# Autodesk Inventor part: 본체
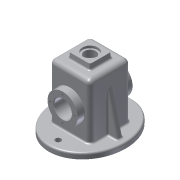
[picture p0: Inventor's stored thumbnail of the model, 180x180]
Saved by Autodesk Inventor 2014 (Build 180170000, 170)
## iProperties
Created: 2017-07
Part Number: 본체
Material: 알루미늄 6061
Document SubType Name: Modeling
Designer: user
Density: 2.71 g/cm^3
Appearance: 알루미늄 - 평지
Mass: 880.579 g
Surface Area: 992.163 cm^2
Volume: 324.937 cm^3
Author: user
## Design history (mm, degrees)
sketch "스케치1" dims "d0" = 75, "d1" = 65
  geometry: L1 (-99.161, 0)-(101.548, 0); C1 r 5 at (-58, 0); C2 r 5 at (58, 0); 2 further points; 1 other entity
  constraints: 3 point on line, 2 centre point, 2 end point, 1 coincident, 1 horizontal, 2 other
  dimensions: "d2" = 10 diameter of C1; "d3" = 10 diameter of C2; "d4" = 58 distance of point (0, 0) C2.centre; "d5" = 58 distance of point (0, 0) C1.centre
extrude "돌출1" new body sketch "스케치1" distance "d6" = 10; taper "d7" = 0 deg
sketch "스케치2"
  geometry: L1 (37, -37)-(-37, -37); L2 (-37, -37)-(-37, 37); L3 (-37, 37)-(37, 37); L4 (37, 37)-(37, -37); L5 (37, -37)-(-37, 37); L6 (-37, -37)-(37, 37); 1 further point
  constraints: 12 end point, 2 midpoint, 2 parallel, 1 horizontal, 1 perpendicular
  dimensions: "d8" = 74 distance of L2.end L3.end; "d9" = 74 distance of L1.end L2.end
extrude "돌출2" join sketch "스케치2" distance "d10" = 100; taper "d11" = 0 deg
sketch "스케치3"
  geometry: L1 (37, 10)-(-37, 10) reference; L2 (37, 10)-(37, 110) reference; L3 (-37, 110)-(37, 110) reference; L4 (-37, 10)-(-37, 110) reference; L5 (32, 105)-(32, 15); L6 (-32, 15)-(-32, 105); L7 (-32, 105)-(32, 105); L8 (32, 15)-(32, 0); L9 (-32, 15)-(-32, 0); L10 (-32, 0)-(32, 0); 1 further point
  constraints: 12 end point, 2 perpendicular, 1 parallel, 1 other
  dimensions: "d12" = 5 distance between parallel lines of L4 L6
extrude "돌출3" cut sketch "스케치3" stored distance "d13" = 64; taper "d14" = 0 deg
sketch "스케치6"
  geometry: L1 (0, 74)-(100, 74) reference; L2 (100, 74)-(100, 0) reference; L3 (-10, 102)-(-10, -28) reference; C1 r 27.5 at (45, 37); C2 r 16 at (45, 37); 1 further point
  constraints: 2 centre point, 1 coincident
  dimensions: "d25" = 55 diameter of C1; "d26" = 32 diameter of C2; "d27" = 37 distance from line of L1 C2.centre; "d29" = 55 distance from line of L3 C1.centre
extrude "돌출5" join sketch "스케치6" distance "d30" = 13; taper "d31" = 0 deg
sketch "스케치7"
  geometry: L1 (37, 10)-(37, 110) reference; L2 (65, 10)-(-65, 10) reference; L3 (65, 10)-(-65, 10) reference; L4 (-65, 0)-(65, 0) reference; L5 (65, 10)-(65, 0); L6 (55, 10)-(37, 82.194); 1 further point
  constraints: 4 end point, 2 point on line, 1 perpendicular
  dimensions: "d32" = 10 distance from line of L5 L6.start; "d33" = 14 deg angle of L5 L6
feature "리브1" sketch "스케치7" dims "d34" = 1, "d35" = 10, "d36" = 0, "d37" = 0, "d38" = 1, "d39" = 1
sketch "스케치8"
  geometry: L1 (-20, -20)-(20, -20); L2 (20, -20)-(20, 20); L3 (20, 20)-(-20, 20); L4 (-20, 20)-(-20, -20); L5 (-20, -20)-(20, 20); L6 (20, -20)-(-20, 20); 1 further point
  constraints: 12 end point, 2 midpoint, 2 parallel, 1 horizontal, 1 perpendicular
  dimensions: "d41" = 40 distance of L3.end L2.end; "d42" = 40 distance of L2.end L1.end
extrude "돌출6" join sketch "스케치8" distance "d44" = 10; taper "d45" = -5 deg
sketch "스케치9"
  geometry: C1 r 10.5 at (0, 0); C2 r 14 at (0, 0); 1 further point
  constraints: 2 centre point, 2 coincident
  dimensions: "d46" = 21 diameter of C1; "d47" = 28 diameter of C2
extrude "돌출7" cut sketch "스케치9" stored distance "d48" = 10; taper "d49" = 0 deg
extrude "돌출8" cut sketch "스케치9" distance "d50" = 4; taper "d51" = 0 deg
sketch "스케치10"
  geometry: L1 (32, 0)-(32, 105) reference; L2 (-32, 105)-(-32, 0) reference; L3 (76.395, 55)-(-68.157, 55); L4 (0, -17.114)-(0, 133.435); L5 (-37, 110)-(37, 110) reference; L6 (32, 82.5)-(25.146, 75.646); L7 (25, 75.293)-(25, 55); L8 (32, 82.5)-(32, 55); L9 (25, 55)-(32, 55); L10 (-32, 82.5)-(-25, 75.5); L11 (-25, 75.5)-(-25, 55); L12 (-32, 82.5)-(-32, 55); L13 (-25, 55)-(-32, 55); A1 r 0.5 centre (25.5, 75.293) between (25.146, 75.646) and (25, 75.293); 2 further points
  constraints: 20 end point, 11 point on line, 5 perpendicular, 3 symmetric about line, 2 point on circle, 2 tangent, 1 centre point
  dimensions: "d52" = 55 distance between parallel lines of L5 L3; "d53" = 7 distance between parallel lines of L1 L7; "d54" = 135 deg angle of L1 L6; "d55" = 55 diameter of L6.start L3; "d72" = 0.5 radius of A1
revolve "회전1" sketch "스케치10" stored, may be unused: angle "d60" = 90 deg
sketch "스케치11"
  geometry: C1 r 16 at (0, 0) reference; C2 r 27.5 at (0, 0) reference; C3 r 16 at (0, 0); 1 further point
  constraints: 1 centre point, 1 coincident
  dimensions: "d61" = 32 diameter of C3
extrude "돌출9" cut sketch "스케치11" stored distance "d62" = 4; taper "d63" = 0 deg
sketch "스케치12"
  geometry: C1 r 16 at (0, 0) reference; C2 r 27.5 at (0, 0) reference; A1 r 22.5 centre (0, 0) between (22.5, 0) and (0, 22.5); 3 further points
  constraints: 4 point on circle, 1 centre point, 1 coincident
  dimensions: "d64" = 45 diameter of A1
hole "구멍1" sketch "스케치12" at (22.5, 0), (0, 22.5), (0, -22.5), (-22.5, 0) diameter "d65" = 3.242; stored, may be unused: countersink angle "d69" = 90 deg, drill point angle "d71" = 118 deg; dims "d66" = 8, "d67" = 4, "d68" = 2, "d70" = 10
fillet "모깎기1" dims "d73" = 8
fillet "모깎기2" dims "d74" = 8
fillet "모깎기3" dims "d75" = 3
fillet "모깎기4" dims "d76" = 3
fillet "모깎기5" dims "d77" = 3
fillet "모깎기6" dims "d78" = 3
fillet "모깎기7" dims "d79" = 3
fillet "모깎기8" dims "d80" = 3
fillet "모깎기9" dims "d81" = 3
fillet "모깎기10" dims "d82" = 3
chamfer "모따기1" distance "d83" = 1; stored, may be unused: second distance "d84" = 2, angle "d85" = 45 deg
fillet "모깎기11" dims "d86" = 0.5
fillet "모깎기12" dims "d87" = 0.5
fillet "모깎기13" dims "d88" = 0.5
node "작업 평면1"
sketch "스케치13"
  geometry: L1 (0, -8)-(89, -8) reference; L2 (-18, 45.137)-(-18, 12.863) reference; 3 further points
  constraints: 1 coincident, 1 other
  dimensions: "d90" = 30 distance from line of L2 point (12, 29); "d91" = 37 distance from line of L1 point (12, 29)
feature "엠보싱1" sketch "스케치13" dims "d0" = 75, "d1" = 65, "d2" = 10, "d3" = 10, "d4" = 58, "d5" = 58, "d92" = 0.5, "d93" = 0
fillet "모깎기14" dims "d94" = 3
fillet "모깎기15" dims "d95" = 3
fillet "모깎기16" dims "d96" = 0.5
node "솔리드1"
mirror "대칭2"
mirror "대칭3"
mirror "대칭4"
node "투영된 루프1"
node "투영된 루프4"
node "투영된 루프5"
node "투영된 루프6"
other parameters: "d89" = 162.25
